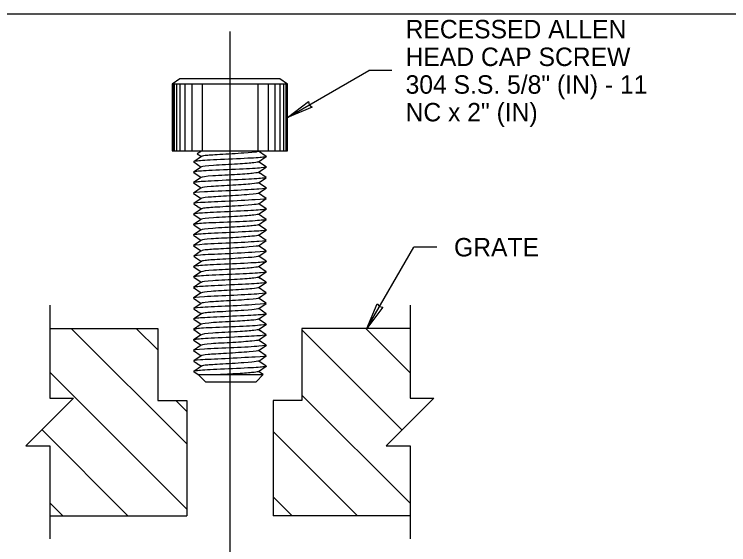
# Model space of a CAD drawing. Extents: x 99862 to 103151, y 100000 to 102076.
# Drawn here: x 101520 to 102140, y 101616 to 102076 of the extents above; entities that cross this region are included whole.
import ezdxf

# ---------------------------------------------------------------- set-up
doc = ezdxf.new("R2010")
doc.units = 0
for name, color, linetype in [('Level 1', 7, 'Continuous'), ('Level 14', 7, 'Continuous'), ('Level 15', 7, 'Continuous'), ('Level 17', 7, 'Continuous'), ('Level 2', 7, 'Continuous'), ('Level 20', 7, 'Continuous')]:
    doc.layers.add(name, color=color, linetype=linetype)

msp = doc.modelspace()

# ---------------------------------------------------------------- linework, layer by layer
at = {"layer": 'Level 1'}
msp.add_lwpolyline([(99862, 99999.5), (103151, 99999.5), (103151, 102075.5), (99862, 102075.5)], close=True, dxfattribs=at)
at = {"layer": 'Level 14'}
for p, q in [((101663.47, 102019.47), (101656.88, 102015.05)), ((101756.88, 102015.05), (101750.3, 102019.47)), ((101756.88, 102015.05), (101656.88, 102015.05)), ((101657.27, 102015.05), (101657.27, 101956.97)), ((101658.47, 102015.05), (101658.47, 101956.97)), ((101660.53, 102015.05), (101660.53, 101956.97)), ((101663.58, 102015.05), (101663.58, 101956.97)), ((101667.85, 102015.05), (101667.85, 101956.97)), ((101673.81, 102015.05), (101673.81, 101956.97)), ((101682.68, 102015.05), (101682.68, 101956.97)), ((101731.09, 102015.05), (101731.09, 101956.97)), ((101739.95, 102015.05), (101739.95, 101956.97)), ((101745.91, 102015.05), (101745.91, 101956.97)), ((101750.18, 102015.05), (101750.18, 101956.97)), ((101753.23, 102015.05), (101753.23, 101956.97)), ((101755.3, 102015.05), (101755.3, 101956.97)), ((101756.49, 102015.05), (101756.49, 101956.97)), ((101682.09, 101956.79), (101678.6, 101954.45)), ((101731.62, 101956.79), (101682.09, 101956.79)), ((101738.45, 101952.21), (101731.62, 101956.79)), ((101682.09, 101952.15), (101675.44, 101947.7)), ((101675.44, 101947.48), (101682.03, 101943.06)), ((101731.78, 101947.59), (101738.45, 101952.06)), ((101738.45, 101943.12), (101731.78, 101947.59)), ((101682.03, 101943.06), (101675.32, 101938.61)), ((101731.72, 101938.5), (101738.45, 101942.97)), ((101675.51, 101938.39), (101682.06, 101934)), ((101738.38, 101934.02), (101731.72, 101938.5)), ((101682.06, 101934), (101675.38, 101929.59)), ((101675.38, 101929.37), (101682.08, 101924.88)), ((101731.78, 101929.41), (101738.45, 101933.81)), ((101738.45, 101924.93), (101731.78, 101929.41)), ((101682.08, 101924.88), (101675.38, 101920.42)), ((101731.72, 101920.28), (101738.45, 101924.79)), ((101675.38, 101920.21), (101682.06, 101915.73)), ((101738.45, 101915.77), (101731.72, 101920.28)), ((101682.06, 101915.73), (101675.44, 101911.33)), ((101731.83, 101911.19), (101738.45, 101915.62)), ((101738.45, 101906.75), (101731.83, 101911.19)), ((101682.09, 101906.7), (101675.44, 101902.24)), ((101731.78, 101902.13), (101738.45, 101906.61)), ((101682.03, 101897.61), (101675.32, 101893.15)), ((101675.44, 101902.02), (101682.03, 101897.61)), ((101731.72, 101893.04), (101738.45, 101897.52)), ((101738.45, 101897.66), (101731.78, 101902.13)), ((101675.51, 101892.93), (101682.06, 101888.54)), ((101738.38, 101888.57), (101731.72, 101893.04)), ((101682.06, 101888.54), (101675.38, 101884.13)), ((101731.78, 101883.95), (101738.45, 101888.35)), ((101675.38, 101883.92), (101682.08, 101879.42)), ((101682.08, 101879.42), (101675.38, 101874.97)), ((101731.72, 101874.82), (101738.45, 101879.33)), ((101738.45, 101879.48), (101731.78, 101883.95)), ((101675.38, 101874.75), (101682.06, 101870.27)), ((101738.45, 101870.32), (101731.72, 101874.82)), ((101682.06, 101870.27), (101675.44, 101865.88)), ((101731.83, 101865.73), (101738.45, 101870.17)), ((101682.09, 101861.24), (101675.44, 101856.79)), ((101731.78, 101856.68), (101738.45, 101861.15)), ((101738.45, 101861.3), (101731.83, 101865.73)), ((101675.44, 101856.57), (101682.03, 101852.16)), ((101738.45, 101852.21), (101731.78, 101856.68)), ((101682.03, 101852.16), (101675.32, 101847.7)), ((101731.72, 101847.59), (101738.45, 101852.06)), ((101682.06, 101843.09), (101675.38, 101838.68)), ((101675.51, 101847.48), (101682.06, 101843.09)), ((101738.38, 101843.12), (101731.72, 101847.59)), ((101731.78, 101838.5), (101738.45, 101842.9)), ((101675.38, 101838.46), (101682.08, 101833.97)), ((101738.45, 101834.02), (101731.78, 101838.5)), ((101682.08, 101833.97), (101675.38, 101829.52)), ((101731.72, 101829.37), (101738.45, 101833.88)), ((101738.45, 101824.86), (101731.72, 101829.37)), ((101675.38, 101829.3), (101682.06, 101824.82)), ((101682.06, 101824.82), (101675.44, 101820.42)), ((101731.83, 101820.28), (101738.45, 101824.72)), ((101738.45, 101815.84), (101731.83, 101820.28)), ((101682.09, 101815.79), (101675.44, 101811.33)), ((101675.44, 101811.12), (101682.03, 101806.7)), ((101731.78, 101811.22), (101738.45, 101815.7)), ((101738.45, 101806.75), (101731.78, 101811.22)), ((101682.03, 101806.7), (101675.32, 101802.24)), ((101731.72, 101802.13), (101738.45, 101806.61)), ((101675.51, 101802.02), (101682.06, 101797.63)), ((101738.38, 101797.66), (101731.72, 101802.13)), ((101682.06, 101797.63), (101675.38, 101793.22)), ((101675.38, 101793.01), (101682.08, 101788.51)), ((101731.78, 101793.04), (101738.45, 101797.44)), ((101738.45, 101788.57), (101731.78, 101793.04)), ((101682.08, 101788.51), (101675.38, 101784.06)), ((101731.72, 101783.92), (101738.45, 101788.42)), ((101675.38, 101783.84), (101682.06, 101779.37)), ((101738.45, 101779.41), (101731.72, 101783.92)), ((101682.06, 101779.37), (101675.44, 101774.97)), ((101731.83, 101774.82), (101738.45, 101779.26)), ((101738.45, 101770.39), (101731.83, 101774.82)), ((101682.09, 101770.33), (101675.44, 101765.88)), ((101731.78, 101765.77), (101738.45, 101770.24)), ((101675.44, 101765.66), (101679.35, 101763.04)), ((101679.35, 101763.04), (101735.85, 101763.04)), ((101685.6, 101756.79), (101679.35, 101763.04)), ((101729.6, 101756.79), (101735.85, 101763.04)), ((101735.85, 101763.04), (101731.78, 101765.77))]:
    msp.add_line(p, q, dxfattribs=at)
for points in [[(101750.3, 102019.47), (101663.47, 102019.47)], [(101656.88, 102015.05), (101656.88, 101956.97), (101682.68, 101956.97)], [(101756.88, 101956.97), (101756.88, 102015.05)], [(101678.6, 101954.45), (101682.09, 101952.15)], [(101731.88, 101956.97), (101756.88, 101956.97)], [(101731.81, 101938.44), (101733.32, 101937.44)], [(101675.44, 101911.12), (101677.15, 101909.95), (101677.78, 101909.59), (101678.04, 101909.37), (101682.09, 101906.7)], [(101731.81, 101892.99), (101733.32, 101891.99)], [(101675.44, 101865.66), (101677.15, 101864.5), (101677.78, 101864.13), (101678.04, 101863.92), (101682.09, 101861.24)], [(101731.81, 101847.53), (101733.32, 101846.53)], [(101675.44, 101820.21), (101677.15, 101819.04), (101677.78, 101818.68), (101678.04, 101818.46), (101682.09, 101815.79)], [(101731.81, 101802.08), (101733.32, 101801.08)], [(101675.44, 101774.75), (101677.15, 101773.59), (101677.78, 101773.22), (101678.04, 101773.01), (101682.09, 101770.33)], [(101685.6, 101756.79), (101729.6, 101756.79)]]:
    msp.add_lwpolyline(points, dxfattribs=at)
for points in [[(101731.62, 101956.57), (101731.62, 101956.57), (101730.92, 101956.13), (101721.68, 101955.19), (101695.88, 101953.73), (101683.86, 101952.93), (101682.4, 101952.35), (101682.28, 101952.28)], [(101738.45, 101952.21), (101738.57, 101952.13), (101738.45, 101951.62), (101725.73, 101950.68), (101692.78, 101949.22), (101676.14, 101948.28), (101675.19, 101947.62), (101675.44, 101947.48)], [(101731.55, 101947.48), (101731.43, 101947.41), (101729.34, 101946.82), (101715.11, 101945.59), (101690.63, 101944.57), (101682.85, 101943.55), (101682.21, 101943.19)], [(101738.45, 101943.12), (101738.7, 101942.97), (101736.8, 101942.39), (101717.32, 101941.01), (101685, 101939.99), (101674.87, 101938.9), (101675.25, 101938.39), (101675.32, 101938.39)], [(101731.55, 101938.39), (101731.43, 101938.32), (101729.34, 101937.73), (101715.11, 101936.5), (101689.8, 101935.41), (101682.09, 101934.39), (101682.09, 101933.95)], [(101738.45, 101934.02), (101738.7, 101933.88), (101737.37, 101933.3), (101719.98, 101932.28), (101687.21, 101930.75), (101675.19, 101929.95), (101675.25, 101929.44), (101675.38, 101929.37)], [(101731.55, 101929.3), (101731.24, 101929.08), (101727.88, 101928.5), (101710.24, 101927.19), (101688.35, 101926.17), (101682.78, 101925.37), (101682.28, 101925.01)], [(101738.45, 101924.93), (101738.83, 101924.72), (101735.22, 101924.06), (101711.12, 101922.61), (101681.45, 101921.52), (101674.75, 101920.64), (101675.38, 101920.21)], [(101731.68, 101920.28), (101731.74, 101919.92), (101726.05, 101919.26), (101702.9, 101917.66), (101685.82, 101916.86), (101682.66, 101916.13), (101682.34, 101915.92)], [(101738.45, 101915.77), (101739.02, 101915.41), (101732, 101914.75), (101701.76, 101913.08), (101678.23, 101912.21), (101675, 101911.41), (101675.44, 101911.12)], [(101731.62, 101911.12), (101731.62, 101911.12), (101730.92, 101910.68), (101721.68, 101909.73), (101695.88, 101908.28), (101683.86, 101907.48), (101682.4, 101906.9), (101682.28, 101906.82)], [(101738.45, 101906.75), (101738.57, 101906.68), (101738.45, 101906.17), (101725.73, 101905.22), (101692.78, 101903.77), (101676.14, 101902.82), (101675.19, 101902.17), (101675.44, 101902.02)], [(101738.45, 101897.66), (101738.7, 101897.52), (101736.8, 101896.93), (101717.32, 101895.55), (101685, 101894.53), (101674.87, 101893.44), (101675.25, 101892.93), (101675.32, 101892.93)], [(101731.55, 101902.02), (101731.43, 101901.95), (101729.34, 101901.37), (101715.11, 101900.13), (101690.63, 101899.12), (101682.85, 101898.1), (101682.21, 101897.73)], [(101731.55, 101892.93), (101731.43, 101892.86), (101729.34, 101892.28), (101715.11, 101891.04), (101689.8, 101889.95), (101682.09, 101888.93), (101682.09, 101888.5)], [(101738.45, 101888.57), (101738.7, 101888.42), (101737.37, 101887.84), (101719.98, 101886.82), (101687.21, 101885.3), (101675.19, 101884.5), (101675.25, 101883.99), (101675.38, 101883.92)], [(101738.45, 101879.48), (101738.83, 101879.26), (101735.22, 101878.61), (101711.12, 101877.15), (101681.45, 101876.06), (101674.75, 101875.19), (101675.38, 101874.75)], [(101731.55, 101883.84), (101731.24, 101883.62), (101727.88, 101883.04), (101710.24, 101881.73), (101688.35, 101880.72), (101682.78, 101879.92), (101682.28, 101879.55)], [(101731.68, 101874.82), (101731.74, 101874.46), (101726.05, 101873.81), (101702.9, 101872.21), (101685.82, 101871.41), (101682.66, 101870.68), (101682.34, 101870.46)], [(101738.45, 101870.32), (101739.02, 101869.95), (101732, 101869.3), (101701.76, 101867.62), (101678.23, 101866.75), (101675, 101865.95), (101675.44, 101865.66)], [(101738.45, 101861.3), (101738.57, 101861.22), (101738.45, 101860.72), (101725.73, 101859.77), (101692.78, 101858.32), (101676.14, 101857.37), (101675.19, 101856.72), (101675.44, 101856.57)], [(101731.62, 101865.66), (101731.62, 101865.66), (101730.92, 101865.22), (101721.68, 101864.28), (101695.88, 101862.82), (101683.86, 101862.02), (101682.4, 101861.44), (101682.28, 101861.37)], [(101731.55, 101856.57), (101731.43, 101856.5), (101729.34, 101855.92), (101715.11, 101854.68), (101690.63, 101853.66), (101682.85, 101852.64), (101682.21, 101852.28)], [(101738.45, 101852.21), (101738.7, 101852.06), (101736.8, 101851.48), (101717.32, 101850.1), (101685, 101849.08), (101674.87, 101847.99), (101675.25, 101847.48), (101675.32, 101847.48)], [(101738.45, 101843.12), (101738.7, 101842.97), (101737.37, 101842.39), (101719.98, 101841.37), (101687.21, 101839.84), (101675.19, 101839.04), (101675.25, 101838.53), (101675.38, 101838.46)], [(101731.55, 101847.48), (101731.43, 101847.41), (101729.34, 101846.82), (101715.11, 101845.59), (101689.8, 101844.5), (101682.09, 101843.48), (101682.09, 101843.04)], [(101731.55, 101838.39), (101731.24, 101838.17), (101727.88, 101837.59), (101710.24, 101836.28), (101688.35, 101835.26), (101682.78, 101834.46), (101682.28, 101834.1)], [(101738.45, 101834.02), (101738.83, 101833.81), (101735.22, 101833.15), (101711.12, 101831.7), (101681.45, 101830.61), (101674.75, 101829.73), (101675.38, 101829.3)], [(101731.68, 101829.37), (101731.74, 101829.01), (101726.05, 101828.35), (101702.9, 101826.75), (101685.82, 101825.95), (101682.66, 101825.22), (101682.34, 101825.01)], [(101738.45, 101824.86), (101739.02, 101824.5), (101732, 101823.84), (101701.76, 101822.17), (101678.23, 101821.3), (101675, 101820.5), (101675.44, 101820.21)], [(101731.62, 101820.21), (101731.62, 101820.21), (101730.92, 101819.77), (101721.68, 101818.82), (101695.88, 101817.37), (101683.86, 101816.57), (101682.4, 101815.99), (101682.28, 101815.92)], [(101738.45, 101815.84), (101738.57, 101815.77), (101738.45, 101815.26), (101725.73, 101814.32), (101692.78, 101812.86), (101676.14, 101811.92), (101675.19, 101811.26), (101675.44, 101811.12)], [(101731.55, 101811.12), (101731.43, 101811.04), (101729.34, 101810.46), (101715.11, 101809.22), (101690.63, 101808.21), (101682.85, 101807.19), (101682.21, 101806.82)], [(101738.45, 101806.75), (101738.7, 101806.61), (101736.8, 101806.02), (101717.32, 101804.64), (101685, 101803.62), (101674.87, 101802.53), (101675.25, 101802.02), (101675.32, 101802.02)], [(101731.55, 101802.02), (101731.43, 101801.95), (101729.34, 101801.37), (101715.11, 101800.13), (101689.8, 101799.04), (101682.09, 101798.02), (101682.09, 101797.59)], [(101738.45, 101797.66), (101738.7, 101797.52), (101737.37, 101796.93), (101719.98, 101795.92), (101687.21, 101794.39), (101675.19, 101793.59), (101675.25, 101793.08), (101675.38, 101793.01)], [(101731.55, 101792.93), (101731.24, 101792.72), (101727.88, 101792.13), (101710.24, 101790.82), (101688.35, 101789.81), (101682.78, 101789.01), (101682.28, 101788.64)], [(101738.45, 101788.57), (101738.83, 101788.35), (101735.22, 101787.7), (101711.12, 101786.24), (101681.45, 101785.15), (101674.75, 101784.28), (101675.38, 101783.84)], [(101731.68, 101783.92), (101731.74, 101783.55), (101726.05, 101782.9), (101702.9, 101781.3), (101685.82, 101780.5), (101682.66, 101779.77), (101682.34, 101779.55)], [(101738.45, 101779.41), (101739.02, 101779.04), (101732, 101778.39), (101701.76, 101776.72), (101678.23, 101775.84), (101675, 101775.04), (101675.44, 101774.75)], [(101731.62, 101774.75), (101731.62, 101774.75), (101730.92, 101774.32), (101721.68, 101773.37), (101695.88, 101771.92), (101683.86, 101771.12), (101682.4, 101770.53), (101682.28, 101770.46)], [(101738.45, 101770.39), (101738.57, 101770.32), (101738.45, 101769.81), (101725.73, 101768.86), (101692.78, 101767.41), (101676.14, 101766.46), (101675.19, 101765.81), (101675.44, 101765.66)], [(101731.55, 101765.66), (101731.43, 101765.59), (101729.34, 101765.01), (101717.17, 101763.95), (101703.67, 101763.31), (101698.78, 101763.04)]]:
    msp.add_open_spline(points, degree=3, dxfattribs=at)
at = {"layer": 'Level 15'}
for p, q in [((101706.88, 102060.7), (101706.88, 101405.72)), ((101756.88, 101986.01), (101827.25, 102026.63)), ((101847.25, 102026.63), (101827.25, 102026.63)), ((101825.65, 101803.15), (101866.27, 101873.52)), ((101886.27, 101873.52), (101866.27, 101873.52))]:
    msp.add_line(p, q, dxfattribs=at)
for points in [[(101756.88, 101986.01), (101775.16, 102000.01), (101775.74, 101996.89), (101778.15, 101994.84)], [(101825.65, 101803.15), (101834.48, 101824.42), (101836.54, 101822.01), (101839.65, 101821.43)]]:
    msp.add_lwpolyline(points, close=True, dxfattribs=at)
for points in [[(101550.62, 101823.15), (101550.62, 101742.55), (101571.26, 101742.55), (101529.97, 101701.25), (101550.62, 101701.25), (101550.62, 101620.65)], [(101863.15, 101823.15), (101863.15, 101742.55), (101883.8, 101742.55), (101842.5, 101701.25), (101863.15, 101701.25), (101863.15, 101620.65)]]:
    msp.add_lwpolyline(points, dxfattribs=at)
at = {"layer": 'Level 17'}
for p, q in [((101669.38, 101702.89), (101569.12, 101803.15)), ((101644.38, 101784.45), (101625.69, 101803.15)), ((101856.23, 101714.99), (101769.38, 101801.84)), ((101863.15, 101764.64), (101824.64, 101803.15)), ((101669.38, 101646.32), (101550.62, 101765.08)), ((101863.15, 101651.5), (101769.38, 101745.27)), ((101669.38, 101731.17), (101659.9, 101740.65)), ((101618.48, 101640.65), (101543.92, 101715.21)), ((101817.43, 101640.65), (101744.38, 101713.7)), ((101760.86, 101640.65), (101744.38, 101657.13)), ((101561.91, 101640.65), (101550.62, 101651.95))]:
    msp.add_line(p, q, dxfattribs=at)
at = {"layer": 'Level 2'}
for p, q in [((101550.62, 101803.15), (101644.38, 101803.15)), ((101644.38, 101803.15), (101644.38, 101740.65)), ((101769.38, 101803.15), (101769.38, 101740.65)), ((101863.15, 101803.15), (101769.38, 101803.15)), ((101644.38, 101740.65), (101669.38, 101740.65)), ((101669.38, 101740.65), (101669.38, 101640.65)), ((101769.38, 101740.65), (101744.38, 101740.65)), ((101744.38, 101740.65), (101744.38, 101640.65)), ((101550.62, 101640.65), (101669.38, 101640.65)), ((101863.15, 101640.65), (101744.38, 101640.65))]:
    msp.add_line(p, q, dxfattribs=at)

# ---------------------------------------------------------------- texts
at = {"layer": 'Level 20'}
for s, p in [('RECESSED ALLEN', (101859.25, 102054.63)), ('HEAD CAP SCREW', (101859.25, 102030.63)), ('304 S.S. 5/8" (IN) - 11', (101859.25, 102006.63)), ('NC x 2" (IN)', (101859.25, 101982.63)), ('GRATE', (101901.27, 101865.52))]:
    msp.add_text(s, height=16, rotation=360, dxfattribs=at).set_placement(p)

doc.saveas('drawing.dxf')
